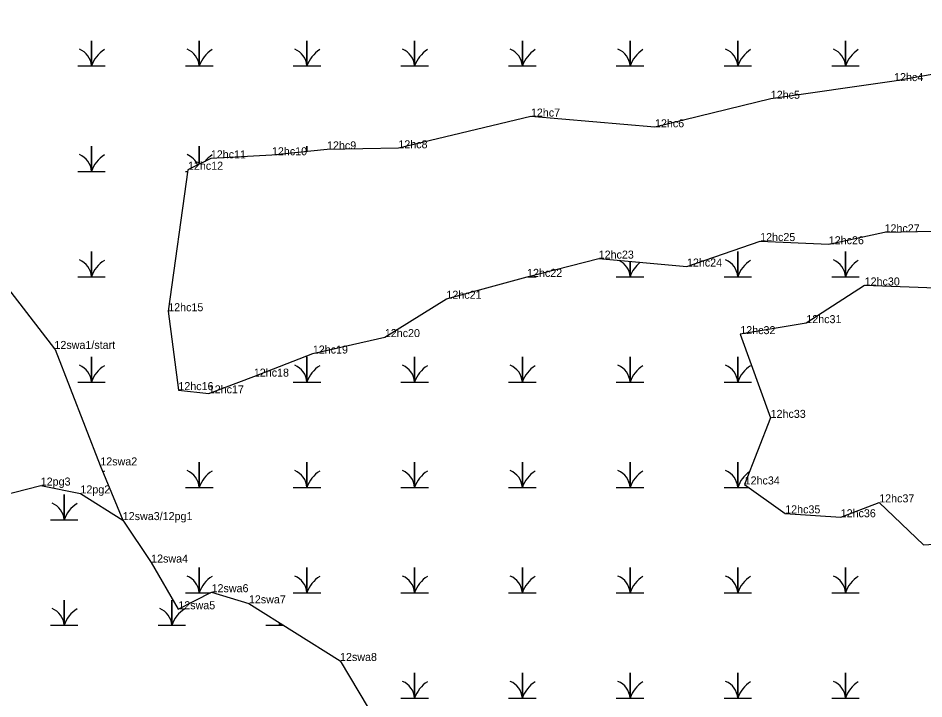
# Model space of a CAD drawing. Extents: x 2072529 to 2268796, y 436423 to 470406.
# Drawn here: x 2229344 to 2229910, y 451056 to 451481 of the extents above; entities that cross this region are included whole.
import ezdxf

# ---------------------------------------------------------------- set-up
doc = ezdxf.new("R2010")
doc.units = 0
for name, color, linetype in [('Exist Environmental Wetland Boundary Cogo Comment', 7, 'Continuous'), ('Exist Environmental Wetland Boundary Cogo Point CELL', 7, 'Continuous'), ('Exist Hydro Jurisdictional Stream or Body of Water NEU Mitigable Cogo Comment', 7, 'Continuous'), ('Old_Level_20', 7, 'Continuous'), ('Old_Level_52', 7, 'Continuous')]:
    doc.layers.add(name, color=color, linetype=linetype)

msp = doc.modelspace()

# ---------------------------------------------------------------- linework, layer by layer
at = {"layer": 'Exist Environmental Wetland Boundary Cogo Point CELL'}
for points in [[(2229381.53, 451450.88), (2229390.13, 451450.88), (2229390.13, 451466.66), (2229390.13, 451450.88), (2229398.73, 451450.88)], [(2229448.78, 451450.88), (2229457.38, 451450.88), (2229457.38, 451466.66), (2229457.38, 451450.88), (2229465.98, 451450.88)], [(2229516.03, 451450.88), (2229524.63, 451450.88), (2229524.63, 451466.66), (2229524.63, 451450.88), (2229533.23, 451450.88)], [(2229583.28, 451450.88), (2229591.88, 451450.88), (2229591.88, 451466.66), (2229591.88, 451450.88), (2229600.48, 451450.88)], [(2229650.53, 451450.88), (2229659.13, 451450.88), (2229659.13, 451466.66), (2229659.13, 451450.88), (2229667.73, 451450.88)], [(2229717.78, 451450.88), (2229726.38, 451450.88), (2229726.38, 451466.66), (2229726.38, 451450.88), (2229734.98, 451450.88)], [(2229785.03, 451450.88), (2229793.63, 451450.88), (2229793.63, 451466.66), (2229793.63, 451450.88), (2229802.23, 451450.88)], [(2229852.28, 451450.88), (2229860.88, 451450.88), (2229860.88, 451466.66), (2229860.88, 451450.88), (2229869.48, 451450.88)], [(2229381.53, 451385.08), (2229390.13, 451385.08), (2229390.13, 451400.86), (2229390.13, 451385.08), (2229398.73, 451385.08)], [(2229457.38, 451389.58), (2229457.38, 451400.86), (2229457.38, 451389.58)], [(2229524.63, 451397.46), (2229524.63, 451400.86), (2229524.63, 451397.46)], [(2229448.78, 451385.08), (2229450.2, 451385.08)], [(2229381.53, 451319.28), (2229390.13, 451319.28), (2229390.13, 451335.06), (2229390.13, 451319.28), (2229398.73, 451319.28)], [(2229785.03, 451319.28), (2229793.63, 451319.28), (2229793.63, 451335.06), (2229793.63, 451319.28), (2229802.23, 451319.28)], [(2229852.28, 451319.28), (2229860.88, 451319.28), (2229860.88, 451335.06), (2229860.88, 451319.28), (2229869.48, 451319.28)], [(2229717.78, 451319.28), (2229726.38, 451319.28), (2229726.38, 451328.82)], [(2229726.38, 451328.82), (2229726.38, 451319.28), (2229734.98, 451319.28)], [(2229662.45, 451319.28), (2229667.73, 451319.28)], [(2229381.53, 451253.48), (2229390.13, 451253.48), (2229390.13, 451269.26), (2229390.13, 451253.48), (2229398.73, 451253.48)], [(2229516.03, 451253.48), (2229524.63, 451253.48), (2229524.63, 451269.26), (2229524.63, 451253.48), (2229533.23, 451253.48)], [(2229583.28, 451253.48), (2229591.88, 451253.48), (2229591.88, 451269.26), (2229591.88, 451253.48), (2229600.48, 451253.48)], [(2229650.53, 451253.48), (2229659.13, 451253.48), (2229659.13, 451269.26), (2229659.13, 451253.48), (2229667.73, 451253.48)], [(2229717.78, 451253.48), (2229726.38, 451253.48), (2229726.38, 451269.26), (2229726.38, 451253.48), (2229734.98, 451253.48)], [(2229785.03, 451253.48), (2229793.63, 451253.48), (2229793.63, 451269.26), (2229793.63, 451253.48), (2229802.23, 451253.48)], [(2229448.78, 451187.68), (2229457.38, 451187.68), (2229457.38, 451203.46), (2229457.38, 451187.68), (2229465.98, 451187.68)], [(2229516.03, 451187.68), (2229524.63, 451187.68), (2229524.63, 451203.46), (2229524.63, 451187.68), (2229533.23, 451187.68)], [(2229583.28, 451187.68), (2229591.88, 451187.68), (2229591.88, 451203.46), (2229591.88, 451187.68), (2229600.48, 451187.68)], [(2229650.53, 451187.68), (2229659.13, 451187.68), (2229659.13, 451203.46), (2229659.13, 451187.68), (2229667.73, 451187.68)], [(2229717.78, 451187.68), (2229726.38, 451187.68), (2229726.38, 451203.46), (2229726.38, 451187.68), (2229734.98, 451187.68)], [(2229785.03, 451187.68), (2229793.63, 451187.68), (2229793.63, 451203.46), (2229793.63, 451187.68), (2229800.53, 451187.68)], [(2229364.44, 451167.39), (2229373.04, 451167.39), (2229373.04, 451183.17), (2229373.04, 451167.39), (2229381.64, 451167.39)], [(2229448.78, 451121.88), (2229457.38, 451121.88), (2229457.38, 451137.66), (2229457.38, 451121.88), (2229464.39, 451121.88)], [(2229516.03, 451121.88), (2229524.63, 451121.88), (2229524.63, 451137.66), (2229524.63, 451121.88), (2229533.23, 451121.88)], [(2229583.28, 451121.88), (2229591.88, 451121.88), (2229591.88, 451137.66), (2229591.88, 451121.88), (2229600.48, 451121.88)], [(2229650.53, 451121.88), (2229659.13, 451121.88), (2229659.13, 451137.66), (2229659.13, 451121.88), (2229667.73, 451121.88)], [(2229717.78, 451121.88), (2229726.38, 451121.88), (2229726.38, 451137.66), (2229726.38, 451121.88), (2229734.98, 451121.88)], [(2229785.03, 451121.88), (2229793.63, 451121.88), (2229793.63, 451137.66), (2229793.63, 451121.88), (2229802.23, 451121.88)], [(2229852.28, 451121.88), (2229860.88, 451121.88), (2229860.88, 451137.66), (2229860.88, 451121.88), (2229869.48, 451121.88)], [(2229364.44, 451101.59), (2229373.04, 451101.59), (2229373.04, 451117.37), (2229373.04, 451101.59), (2229381.64, 451101.59)], [(2229431.69, 451101.59), (2229440.29, 451101.59), (2229440.29, 451117.37), (2229440.29, 451101.59), (2229448.89, 451101.59)], [(2229498.94, 451101.59), (2229507.54, 451101.59), (2229507.54, 451103.18)], [(2229507.54, 451103.18), (2229507.54, 451101.59), (2229510.05, 451101.59)], [(2229583.28, 451056.08), (2229591.88, 451056.08), (2229591.88, 451071.86), (2229591.88, 451056.08), (2229600.48, 451056.08)], [(2229650.53, 451056.08), (2229659.13, 451056.08), (2229659.13, 451071.86), (2229659.13, 451056.08), (2229667.73, 451056.08)], [(2229717.78, 451056.08), (2229726.38, 451056.08), (2229726.38, 451071.86), (2229726.38, 451056.08), (2229734.98, 451056.08)], [(2229785.03, 451056.08), (2229793.63, 451056.08), (2229793.63, 451071.86), (2229793.63, 451056.08), (2229802.23, 451056.08)], [(2229852.28, 451056.08), (2229860.88, 451056.08), (2229860.88, 451071.86), (2229860.88, 451056.08), (2229869.48, 451056.08)]]:
    msp.add_lwpolyline(points, dxfattribs=at)
for centre, radius, start, end in [((2229377.86, 451449.99), 12.3, 4.1403, 67.535), ((2229445.11, 451449.99), 12.3, 4.1403, 67.535), ((2229512.36, 451449.99), 12.3, 4.1403, 67.535), ((2229579.61, 451449.99), 12.3, 4.1403, 67.535), ((2229646.86, 451449.99), 12.3, 4.1403, 67.535), ((2229714.11, 451449.99), 12.3, 4.1403, 67.535), ((2229781.36, 451449.99), 12.3, 4.1403, 67.535), ((2229848.61, 451449.99), 12.3, 4.1403, 67.535), ((2229408.37, 451444.82), 19.22, 122.1274, 161.6222), ((2229475.62, 451444.82), 19.22, 122.1274, 161.6222), ((2229542.87, 451444.82), 19.22, 122.1274, 161.6222), ((2229610.12, 451444.82), 19.22, 122.1274, 161.6222), ((2229677.37, 451444.82), 19.22, 122.1274, 161.6222), ((2229744.62, 451444.82), 19.22, 122.1274, 161.6222), ((2229811.87, 451444.82), 19.22, 122.1274, 161.6222), ((2229879.12, 451444.82), 19.22, 122.1274, 161.6222), ((2229377.86, 451384.19), 12.3, 4.1403, 67.535), ((2229408.37, 451379.02), 19.22, 122.1274, 161.6222), ((2229445.11, 451384.19), 12.3, 23.4595, 67.535), ((2229475.62, 451379.02), 19.22, 122.1274, 140.3031), ((2229377.86, 451318.39), 12.3, 4.1403, 67.535), ((2229408.37, 451313.22), 19.22, 122.1274, 161.6222), ((2229714.11, 451318.39), 12.3, 4.1403, 64.0157), ((2229744.62, 451313.22), 19.22, 128.5066, 161.6222), ((2229781.36, 451318.39), 12.3, 4.1403, 67.535), ((2229811.87, 451313.22), 19.22, 122.1274, 161.6222), ((2229848.61, 451318.39), 12.3, 4.1403, 67.535), ((2229879.12, 451313.22), 19.22, 122.1274, 161.6222), ((2229377.86, 451252.59), 12.3, 4.1403, 67.535), ((2229408.37, 451247.42), 19.22, 122.1274, 161.6222), ((2229512.36, 451252.59), 12.3, 4.1403, 67.535), ((2229542.87, 451247.42), 19.22, 122.1274, 161.6222), ((2229579.61, 451252.59), 12.3, 4.1403, 67.535), ((2229610.12, 451247.42), 19.22, 122.1274, 161.6222), ((2229646.86, 451252.59), 12.3, 4.1403, 67.535), ((2229677.37, 451247.42), 19.22, 122.1274, 161.6222), ((2229714.11, 451252.59), 12.3, 4.1403, 67.535), ((2229744.62, 451247.42), 19.22, 122.1274, 161.6222), ((2229781.36, 451252.59), 12.3, 4.1403, 67.535), ((2229811.87, 451247.42), 19.22, 122.1274, 161.6222), ((2229408.37, 451181.62), 19.22, 122.1274, 125.1894), ((2229445.11, 451186.79), 12.3, 4.1403, 67.535), ((2229475.62, 451181.62), 19.22, 122.1274, 161.6222), ((2229512.36, 451186.79), 12.3, 4.1403, 67.535), ((2229542.87, 451181.62), 19.22, 122.1274, 161.6222), ((2229579.61, 451186.79), 12.3, 4.1403, 67.535), ((2229610.12, 451181.62), 19.22, 122.1274, 161.6222), ((2229646.86, 451186.79), 12.3, 4.1403, 67.535), ((2229677.37, 451181.62), 19.22, 122.1274, 161.6222), ((2229714.11, 451186.79), 12.3, 4.1403, 67.535), ((2229744.62, 451181.62), 19.22, 122.1274, 161.6222), ((2229781.36, 451186.79), 12.3, 4.1403, 67.535), ((2229811.87, 451181.62), 19.22, 124.3668, 161.6222), ((2229360.77, 451166.5), 12.3, 4.1403, 67.535), ((2229391.28, 451161.33), 19.22, 122.1274, 161.6222), ((2229445.11, 451120.99), 12.3, 4.1403, 67.535), ((2229475.62, 451115.82), 19.22, 122.1274, 161.6222), ((2229512.36, 451120.99), 12.3, 4.1403, 67.535), ((2229542.87, 451115.82), 19.22, 122.1274, 161.6222), ((2229579.61, 451120.99), 12.3, 4.1403, 67.535), ((2229610.12, 451115.82), 19.22, 122.1274, 161.6222), ((2229646.86, 451120.99), 12.3, 4.1403, 67.535), ((2229677.37, 451115.82), 19.22, 122.1274, 161.6222), ((2229714.11, 451120.99), 12.3, 4.1403, 67.535), ((2229744.62, 451115.82), 19.22, 122.1274, 161.6222), ((2229781.36, 451120.99), 12.3, 4.1403, 67.535), ((2229811.87, 451115.82), 19.22, 122.1274, 161.6222), ((2229848.61, 451120.99), 12.3, 4.1403, 67.535), ((2229879.12, 451115.82), 19.22, 122.1274, 161.6222), ((2229360.77, 451100.7), 12.3, 4.1403, 67.535), ((2229391.28, 451095.53), 19.22, 122.1274, 161.6222), ((2229428.02, 451100.7), 12.3, 4.1403, 67.535), ((2229458.53, 451095.53), 19.22, 122.1274, 161.6222), ((2229495.27, 451100.7), 12.3, 4.1403, 12.372), ((2229525.78, 451095.53), 19.22, 157.5364, 161.6222), ((2229579.61, 451055.19), 12.3, 4.1403, 67.535), ((2229610.12, 451050.02), 19.22, 122.1274, 161.6222), ((2229646.86, 451055.19), 12.3, 4.1403, 67.535), ((2229677.37, 451050.02), 19.22, 122.1274, 161.6222), ((2229714.11, 451055.19), 12.3, 4.1403, 67.535), ((2229744.62, 451050.02), 19.22, 122.1274, 161.6222), ((2229781.36, 451055.19), 12.3, 4.1403, 67.535), ((2229811.87, 451050.02), 19.22, 122.1274, 161.6222), ((2229848.61, 451055.19), 12.3, 4.1403, 67.535), ((2229879.12, 451050.02), 19.22, 122.1274, 161.6222)]:
    msp.add_arc(centre, radius, start, end, dxfattribs=at)
at = {"layer": 'Old_Level_20'}
for p, q in [((2229891.22, 451441.44), (2229891.22, 451441.44)), ((2229814.23, 451430.41), (2229814.23, 451430.41)), ((2229664.46, 451419.29), (2229664.46, 451419.29)), ((2229741.93, 451412.59), (2229741.93, 451412.59)), ((2229581.7, 451399.48), (2229581.7, 451399.48)), ((2229502.76, 451395.12), (2229502.76, 451395.12)), ((2229537.17, 451398.8), (2229537.17, 451398.8)), ((2229464.62, 451393.18), (2229464.62, 451393.18)), ((2229450.34, 451386.07), (2229450.34, 451386.07)), ((2229885.27, 451347.01), (2229885.27, 451347.01)), ((2229807.6, 451341.54), (2229807.6, 451341.54)), ((2229850.43, 451339.56), (2229850.43, 451339.56)), ((2229706.78, 451330.59), (2229706.78, 451330.59)), ((2229761.9, 451325.62), (2229761.9, 451325.62)), ((2229662.06, 451319.18), (2229662.06, 451319.18)), ((2229872.85, 451313.81), (2229872.85, 451313.81)), ((2229611.71, 451305.52), (2229611.71, 451305.52)), ((2229438, 451297.72), (2229438, 451297.72)), ((2229836.42, 451290.28), (2229836.42, 451290.28)), ((2229573.25, 451281.58), (2229573.25, 451281.58)), ((2229795.19, 451283.41), (2229795.19, 451283.41)), ((2229528.29, 451271.29), (2229528.29, 451271.29)), ((2229491.46, 451256.89), (2229491.46, 451256.89)), ((2229444.35, 451248.44), (2229444.35, 451248.44)), ((2229463.32, 451246.43), (2229463.32, 451246.43)), ((2229814.13, 451231.12), (2229814.13, 451231.12)), ((2229395.61, 451201.43), (2229395.61, 451201.43)), ((2229358.41, 451188.85), (2229358.41, 451188.85)), ((2229797.92, 451189.54), (2229797.92, 451189.54)), ((2229383.21, 451183.94), (2229383.21, 451183.94)), ((2229881.93, 451178.34), (2229881.93, 451178.34)), ((2229409.63, 451167.28), (2229409.63, 451167.28)), ((2229409.63, 451167.28), (2229409.63, 451167.28)), ((2229823.24, 451171.48), (2229823.24, 451171.48)), ((2229857.88, 451169.06), (2229857.88, 451169.06)), ((2229909.57, 451151.78), (2229909.57, 451151.78)), ((2229427.34, 451140.76), (2229427.34, 451140.76)), ((2229465.09, 451122.24), (2229465.09, 451122.24)), ((2229444.31, 451111.6), (2229444.31, 451111.6)), ((2229488.39, 451115.29), (2229488.39, 451115.29)), ((2229545.28, 451079.31), (2229545.28, 451079.31))]:
    msp.add_line(p, q, dxfattribs=at)
for points in [[(2229983.68, 451457.72), (2229891.22, 451441.44), (2229814.23, 451430.41), (2229741.93, 451412.59), (2229664.46, 451419.29), (2229581.7, 451399.48), (2229537.17, 451398.8), (2229502.76, 451395.12), (2229464.62, 451393.18), (2229450.34, 451386.07), (2229438, 451297.72), (2229444.35, 451248.44), (2229463.32, 451246.43), (2229491.46, 451256.89), (2229528.29, 451271.29), (2229573.25, 451281.58), (2229611.71, 451305.52), (2229662.06, 451319.18), (2229706.78, 451330.59), (2229761.9, 451325.62), (2229807.6, 451341.54), (2229850.43, 451339.56), (2229885.27, 451347.01), (2229936.8, 451348.22)], [(2229922.92, 451311.91), (2229872.85, 451313.81), (2229836.42, 451290.28), (2229795.19, 451283.41), (2229814.13, 451231.12), (2229797.92, 451189.54), (2229823.24, 451171.48), (2229857.88, 451169.06), (2229881.93, 451178.34), (2229909.57, 451151.78), (2229943.66, 451154.01)], [(2228751.2, 450943.22), (2228792.46, 451065.26), (2228824.23, 451160.93), (2228849.17, 451242.54), (2228861.2, 451273.86), (2228933.18, 451259.19), (2228976.66, 451247.91), (2229046.17, 451240.44), (2229130.67, 451234.48), (2229187.59, 451236.41), (2229261.98, 451242.15), (2229261.21, 451201.73), (2229230.76, 451193.83), (2229279.73, 451176.25), (2229308.66, 451176.22), (2229358.41, 451188.85), (2229383.21, 451183.94), (2229409.63, 451167.28)], [(2229366.97, 451274.18), (2229367.34, 451273.73), (2229366.97, 451274.18)]]:
    msp.add_lwpolyline(points, dxfattribs=at)
at = {"layer": 'Old_Level_52'}
msp.add_lwpolyline([(2228933.83, 451795.85), (2228976.21, 451773.86), (2229000.02, 451702.66), (2229023.31, 451649.28), (2229046.5, 451600.21), (2229079.47, 451548.53), (2229127.8, 451482.28), (2229190.08, 451451.65), (2229267.38, 451400.92), (2229294.81, 451367.69), (2229366.97, 451274.18), (2229367.34, 451273.73), (2229395.61, 451201.43), (2229409.63, 451167.28), (2229427.34, 451140.76), (2229444.31, 451111.6), (2229465.09, 451122.24), (2229488.39, 451115.29), (2229545.28, 451079.31), (2229562.75, 451050.09)], dxfattribs=at)

# ---------------------------------------------------------------- texts
at = {"layer": 'Exist Environmental Wetland Boundary Cogo Comment'}
for s, p in [('12hc4', (2229891.22, 451441.44)), ('12hc5', (2229814.23, 451430.41)), ('12hc7', (2229664.46, 451419.29)), ('12hc6', (2229741.93, 451412.59)), ('12hc10', (2229502.76, 451395.12)), ('12hc9', (2229537.17, 451398.8)), ('12hc8', (2229581.7, 451399.48)), ('12hc11', (2229464.62, 451393.18)), ('12hc12', (2229450.34, 451386.07)), ('12hc27', (2229885.27, 451347.01)), ('12hc25', (2229807.6, 451341.54)), ('12hc26', (2229850.43, 451339.56)), ('12hc23', (2229706.78, 451330.59)), ('12hc24', (2229761.9, 451325.62)), ('12hc22', (2229662.06, 451319.18)), ('12hc30', (2229872.85, 451313.81)), ('12hc21', (2229611.71, 451305.52)), ('12hc15', (2229438, 451297.72)), ('12hc31', (2229836.42, 451290.28)), ('12hc20', (2229573.25, 451281.58)), ('12hc32', (2229795.19, 451283.41)), ('12hc19', (2229528.29, 451271.29)), ('12hc18', (2229491.46, 451256.89)), ('12hc16', (2229444.35, 451248.44)), ('12hc17', (2229463.32, 451246.43)), ('12hc33', (2229814.13, 451231.12)), ('12pg3', (2229358.41, 451188.85)), ('12hc34', (2229797.92, 451189.54)), ('12pg2', (2229383.21, 451183.94)), ('12hc37', (2229881.93, 451178.34)), ('12hc35', (2229823.24, 451171.48)), ('12hc36', (2229857.88, 451169.06))]:
    msp.add_text(s, height=5, dxfattribs=at).set_placement(p)
at = {"layer": 'Exist Hydro Jurisdictional Stream or Body of Water NEU Mitigable Cogo Comment'}
for s, p in [('12swa1/start', (2229366.97, 451274.18)), ('12swa2', (2229395.61, 451201.43)), ('12swa3/12pg1', (2229409.63, 451167.28)), ('12swa4', (2229427.34, 451140.76)), ('12swa6', (2229465.09, 451122.24)), ('12swa5', (2229444.31, 451111.6)), ('12swa7', (2229488.39, 451115.29)), ('12swa8', (2229545.28, 451079.31))]:
    msp.add_text(s, height=5, dxfattribs=at).set_placement(p)

doc.saveas('drawing.dxf')
